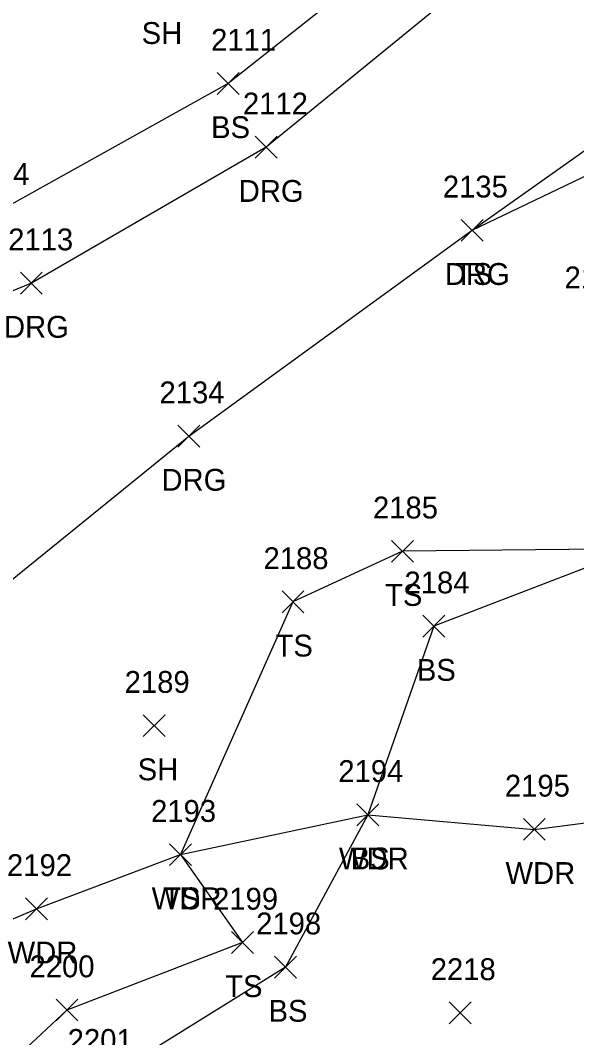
# Model space of a CAD drawing. Extents: x 1501299 to 1502485, y 381423 to 383765.
# Drawn here: x 1501473.5 to 1501524.4, y 383274.3 to 383367.4 of the extents above; entities that cross this region are included whole.
import ezdxf

# ---------------------------------------------------------------- set-up
doc = ezdxf.new("R2010")
doc.units = 0
for name, color, linetype in [('L_A', 7, 'Continuous'), ('L_I', 7, 'Continuous'), ('L_TIC', 7, 'Continuous'), ('LAWA', 7, 'Continuous'), ('LELB', 7, 'Continuous'), ('R_A', 7, 'Continuous'), ('R_I', 7, 'Continuous'), ('R_TIC', 7, 'Continuous'), ('RDG', 7, 'Continuous')]:
    doc.layers.add(name, color=color, linetype=linetype)

msp = doc.modelspace()

# ---------------------------------------------------------------- linework, layer by layer
at = {"layer": 'L_TIC'}
for points in [[(1501491.517, 383360.605), (1501493.517, 383362.605)], [(1501493.517, 383360.605), (1501491.517, 383362.605)], [(1501513.863, 383347.169), (1501515.863, 383349.169)], [(1501515.863, 383347.169), (1501513.863, 383349.169)], [(1501507.471, 383317.793), (1501509.471, 383319.793)], [(1501509.471, 383317.793), (1501507.471, 383319.793)], [(1501497.449, 383313.158), (1501499.449, 383315.158)], [(1501499.449, 383313.158), (1501497.449, 383315.158)], [(1501510.352, 383310.935), (1501512.352, 383312.935)], [(1501512.352, 383310.935), (1501510.352, 383312.935)], [(1501484.749, 383301.833), (1501486.749, 383303.833)], [(1501486.749, 383301.833), (1501484.749, 383303.833)], [(1501504.298, 383293.675), (1501506.298, 383295.675)], [(1501506.298, 383293.675), (1501504.298, 383295.675)], [(1501504.298, 383293.675), (1501506.298, 383295.675)], [(1501506.298, 383293.675), (1501504.298, 383295.675)], [(1501519.544, 383292.338), (1501521.544, 383294.338)], [(1501521.544, 383292.338), (1501519.544, 383294.338)], [(1501487.159, 383290.024), (1501489.159, 383292.024)], [(1501489.159, 383290.024), (1501487.159, 383292.024)], [(1501487.159, 383290.024), (1501489.159, 383292.024)], [(1501489.159, 383290.024), (1501487.159, 383292.024)], [(1501473.969, 383285.067), (1501475.969, 383287.067)], [(1501475.969, 383285.067), (1501473.969, 383287.067)], [(1501492.84, 383281.989), (1501494.84, 383283.989)], [(1501494.84, 383281.989), (1501492.84, 383283.989)], [(1501496.775, 383279.73), (1501498.775, 383281.73)], [(1501498.775, 383279.73), (1501496.775, 383281.73)], [(1501476.762, 383275.802), (1501478.762, 383277.802)], [(1501478.762, 383275.802), (1501476.762, 383277.802)], [(1501512.758, 383275.542), (1501514.758, 383277.542)], [(1501514.758, 383275.542), (1501512.758, 383277.542)]]:
    msp.add_lwpolyline(points, dxfattribs=at)
at = {"layer": 'LAWA'}
msp.add_lwpolyline([(1501455.233, 383277.691), (1501474.969, 383286.067), (1501488.159, 383291.024), (1501505.298, 383294.675), (1501520.544, 383293.338), (1501529.899, 383294.534), (1501540.898, 383298.823), (1501560.179, 383293.041)], dxfattribs=at)
at = {"layer": 'LELB'}
for points in [[(1501466.902, 383480.31), (1501471.599, 383467.813), (1501488.937, 383457.911), (1501495.791, 383450.814), (1501515.889, 383421.068), (1501517.943, 383408.256), (1501520.749, 383388.814), (1501512.356, 383377.307), (1501492.517, 383361.605), (1501470.503, 383349.325), (1501449.875, 383345.736), (1501440.322, 383348.073)], [(1501514.863, 383348.169), (1501532.009, 383356.376), (1501551.241, 383360.865), (1501559.526, 383359.149), (1501577.64, 383333.828), (1501582.97, 383325.895), (1501599.37, 383304.818)], [(1501529.789, 383319.024), (1501508.471, 383318.793), (1501498.449, 383314.158), (1501488.159, 383291.024), (1501493.84, 383282.989), (1501477.762, 383276.802), (1501469.368, 383268.993), (1501481.005, 383249.166), (1501469.559, 383246.339)], [(1501529.789, 383319.024), (1501511.352, 383311.935), (1501505.298, 383294.675), (1501497.775, 383280.73), (1501480.605, 383270.063), (1501487.356, 383250.583), (1501481.065, 383239.917)]]:
    msp.add_lwpolyline(points, dxfattribs=at)
at = {"layer": 'R_TIC'}
for points in [[(1501494.997, 383354.771), (1501496.997, 383356.771)], [(1501496.997, 383354.771), (1501494.997, 383356.771)], [(1501513.863, 383347.169), (1501515.863, 383349.169)], [(1501515.863, 383347.169), (1501513.863, 383349.169)], [(1501473.509, 383342.334), (1501475.509, 383344.334)], [(1501475.509, 383342.334), (1501473.509, 383344.334)], [(1501487.926, 383328.334), (1501489.926, 383330.334)], [(1501489.926, 383328.334), (1501487.926, 383330.334)]]:
    msp.add_lwpolyline(points, dxfattribs=at)
at = {"layer": 'RDG'}
for points in [[(1501532.703, 383406.598), (1501533.377, 383399.877), (1501528.167, 383386.846), (1501516.613, 383372.604), (1501495.997, 383355.771), (1501474.509, 383343.334), (1501449.692, 383333.159), (1501433.053, 383350.151)], [(1501445.866, 383299.066), (1501467.724, 383312.153), (1501488.926, 383329.334), (1501514.863, 383348.169), (1501534.189, 383361.876), (1501549.512, 383366.241), (1501560.323, 383365.298)]]:
    msp.add_lwpolyline(points, dxfattribs=at)

# ---------------------------------------------------------------- texts
at = {"layer": 'L_A'}
for s, p in [('SH', (1501484.602, 383365.222)), ('BS', (1501490.958, 383356.605)), ('TS', (1501513.273, 383343.169)), ('TS', (1501506.881, 383313.793)), ('TS', (1501496.858, 383309.158)), ('BS', (1501509.793, 383306.935)), ('SH', (1501484.237, 383297.833)), ('WDR', (1501502.66, 383289.675)), ('BS', (1501503.739, 383289.675)), ('WDR', (1501517.907, 383288.338)), ('WDR', (1501485.521, 383286.024)), ('TS', (1501486.568, 383286.024)), ('WDR', (1501472.332, 383281.067)), ('TS', (1501492.25, 383277.989)), ('BS', (1501496.216, 383275.73))]:
    msp.add_text(s, height=2, dxfattribs=at).set_placement(p)
at = {"layer": 'L_I'}
for s, p in [('2111', (1501490.959, 383364.605)), ('2114', (1501468.377, 383352.325)), ('2135', (1501512.171, 383351.169)), ('2186', (1501523.315, 383342.856)), ('2185', (1501505.779, 383321.793)), ('2188', (1501495.756, 383317.158)), ('2184', (1501508.659, 383314.935)), ('2189', (1501483.049, 383305.833)), ('2194', (1501502.605, 383297.675)), ('2194', (1501502.605, 383297.675)), ('2195', (1501517.852, 383296.338)), ('2193', (1501485.466, 383294.024)), ('2193', (1501485.466, 383294.024)), ('2192', (1501472.277, 383289.067)), ('2199', (1501491.14, 383285.989)), ('2198', (1501495.083, 383283.73)), ('2200', (1501474.337, 383279.802)), ('2218', (1501511.065, 383279.542)), ('2201', (1501477.833, 383273.063))]:
    msp.add_text(s, height=2, dxfattribs=at).set_placement(p)
at = {"layer": 'R_A'}
for p in [(1501493.486, 383350.771), (1501512.352, 383343.169), (1501471.998, 383338.334), (1501486.414, 383324.334)]:
    msp.add_text('DRG', height=2, dxfattribs=at).set_placement(p)
at = {"layer": 'R_I'}
for s, p in [('2112', (1501493.872, 383358.771)), ('2135', (1501512.171, 383351.169)), ('2113', (1501472.384, 383346.334)), ('2134', (1501486.234, 383332.334))]:
    msp.add_text(s, height=2, dxfattribs=at).set_placement(p)

doc.saveas('drawing.dxf')
